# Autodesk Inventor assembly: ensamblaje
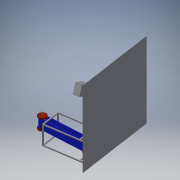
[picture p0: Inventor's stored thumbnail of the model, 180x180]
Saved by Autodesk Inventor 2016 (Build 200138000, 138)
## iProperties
Created: 2016-06
Part Number: ensamblaje
Material: Genérico
Document SubType Name: Assembly
Designer: adm
Author: adm
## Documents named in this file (8)
- C:\Users\adm\Desktop\Alvarez\ensamblaje.iam
- C:\Users\adm\Desktop\Alvarez\eje x2.ipt
- C:\Users\adm\Desktop\Alvarez\cilindro de movimientox2.ipt
- C:\Users\adm\Desktop\Alvarez\rueda del eje(sin movimiento)x4.ipt
- C:\Users\adm\Desktop\Alvarez\faja.ipt
- C:\Users\adm\Desktop\Alvarez\recepcion n°1.ipt
- C:\Users\adm\Desktop\Alvarez\armazon.ipt
- C:\Users\adm\Desktop\Alvarez\tabla.ipt
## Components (12 placed, 7 different names)
1. eje x2:1 — Ángulo:1, Tangente:2, Nivelación:1, Tangente:5, Tangente:6, Ángulo:2, Coincidencia:14
2. eje x2:2 — Ángulo:1, Nivelación:1, Coincidencia:5, Tangente:7, Coincidencia:7, Ángulo:3
3. cilindro de movimientox2:1 — Tangente:7, Coincidencia:9, Coincidencia:10, Coincidencia:11, Tangente:8
4. cilindro de movimientox2:2 — Tangente:2, Coincidencia:3, Coincidencia:4, Tangente:9
5. rueda del eje(sin movimiento)x4:1 — Tangente:6, Coincidencia:3, Coincidencia:13
6. rueda del eje(sin movimiento)x4:2 — Coincidencia:5, Coincidencia:11
7. rueda del eje(sin movimiento)x4:3 — Tangente:5, Coincidencia:4, Ángulo:2
8. rueda del eje(sin movimiento)x4:4 — Coincidencia:7, Coincidencia:9, Coincidencia:10, Coincidencia:12
9. faja:1 — Tangente:8, Ángulo:3, Coincidencia:12, Tangente:9, Coincidencia:13
10. recepcion n°1:1
11. armazon:1 — Coincidencia:14, Coincidencia:15, Nivelación:2
12. tabla:1 — Coincidencia:15, Nivelación:2
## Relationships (22: Mate 11, Tangent 6, Angle 3, Flush 2)
- Ángulo:1 [Angle]: eje x2:1 ↔ eje x2:2
- Tangente:2: eje x2:1 ↔ cilindro de movimientox2:2
- Nivelación:1 [Flush]: eje x2:1 ↔ eje x2:2
- Tangente:5: eje x2:1 ↔ rueda del eje(sin movimiento)x4:3
- Tangente:6: eje x2:1 ↔ rueda del eje(sin movimiento)x4:1
- Coincidencia:3 [Mate]: cilindro de movimientox2:2 ↔ rueda del eje(sin movimiento)x4:1
- Coincidencia:4 [Mate]: cilindro de movimientox2:2 ↔ rueda del eje(sin movimiento)x4:3
- Ángulo:2 [Angle]: eje x2:1 ↔ rueda del eje(sin movimiento)x4:3
- Coincidencia:5 [Mate]: eje x2:2 ↔ rueda del eje(sin movimiento)x4:2
- Tangente:7: eje x2:2 ↔ cilindro de movimientox2:1
- Coincidencia:7 [Mate]: eje x2:2 ↔ rueda del eje(sin movimiento)x4:4
- Coincidencia:9 [Mate]: cilindro de movimientox2:1 ↔ rueda del eje(sin movimiento)x4:4
- Coincidencia:10 [Mate]: cilindro de movimientox2:1 ↔ rueda del eje(sin movimiento)x4:4
- Coincidencia:11 [Mate]: cilindro de movimientox2:1 ↔ rueda del eje(sin movimiento)x4:2
- Tangente:8: cilindro de movimientox2:1 ↔ faja:1
- Ángulo:3 [Angle]: eje x2:2 ↔ faja:1
- Coincidencia:12 [Mate]: rueda del eje(sin movimiento)x4:4 ↔ faja:1
- Tangente:9: cilindro de movimientox2:2 ↔ faja:1
- Coincidencia:13 [Mate]: rueda del eje(sin movimiento)x4:1 ↔ faja:1
- Coincidencia:14 [Mate]: eje x2:1 ↔ armazon:1
- Coincidencia:15 [Mate]: armazon:1 ↔ tabla:1
- Nivelación:2 [Flush]: armazon:1 ↔ tabla:1
